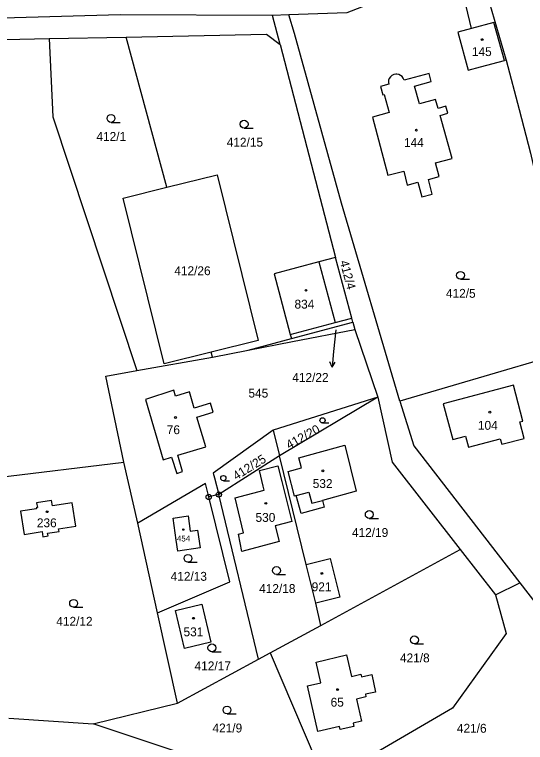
# Model space of a CAD drawing. Extents: x -725728 to -720881, y -1068679 to -1063504.
# Drawn here: x -724297.2 to -724199.5, y -1067188.2 to -1067048.9 of the extents above; entities that cross this region are included whole.
import ezdxf

# ---------------------------------------------------------------- set-up
doc = ezdxf.new("R2010")
doc.units = 0
for name, color, linetype in [('Hranice parcel', 7, 'Continuous'), ('Parcelní čísla', 7, 'Continuous'), ('Pop  PČ popisy', 7, 'Continuous'), ('Vnitřní kresba', 7, 'Continuous'), ('Značky bodu BP', 7, 'Continuous'), ('Značky budov', 7, 'Continuous'), ('Značky kultur', 7, 'Continuous')]:
    doc.layers.add(name, color=color, linetype=linetype)

# ---------------------------------------------------------------- blocks, each defined once
blk = doc.blocks.new('4.02_3')
at = {"layer": 'Značky budov'}
blk.add_circle((-0.001, 0), 0.0175, dxfattribs=at)
blk = doc.blocks.new('4.02_4')
at = {"layer": 'Značky budov'}
blk.add_circle((-0.001, 0), 0.0175, dxfattribs=at)
blk = doc.blocks.new('4.02_2')
at = {"layer": 'Značky budov'}
blk.add_circle((0, 0), 0.0117, dxfattribs=at)
blk = doc.blocks.new('1029_89')
at = {"layer": 'Pop  PČ popisy'}
for p, q in [((0, 0), (-0.031, -0.299)), ((-0.031, -0.299), (-0.071, -0.194)), ((-0.031, -0.299), (0.029, -0.204))]:
    blk.add_line(p, q, dxfattribs=at)
blk = doc.blocks.new('3.04_2')
at = {"layer": 'Značky kultur'}
blk.add_line((0.001, 0), (0.176, 0), dxfattribs=at)
blk.add_circle((0.001, 0.075), 0.075, dxfattribs=at)
blk = doc.blocks.new('3.04_4')
at = {"layer": 'Značky kultur'}
blk.add_line((0, 0), (0.118, 0), dxfattribs=at)
blk.add_circle((0, 0.05), 0.0502, dxfattribs=at)
blk = doc.blocks.new('3.04_5')
at = {"layer": 'Značky kultur'}
blk.add_line((0, 0), (0.118, 0), dxfattribs=at)
blk.add_circle((0, 0.05), 0.0502, dxfattribs=at)
blk = doc.blocks.new('1.05_1')
at = {"layer": 'Značky bodu BP'}
for radius in [0.05, 0.00303]:
    blk.add_circle((0, 0), radius, dxfattribs=at)

msp = doc.modelspace()

# ---------------------------------------------------------------- linework, layer by layer
at = {"layer": 'Hranice parcel'}
for p, q in [((-724244.76, -1067048.93), (-724247.87, -1067049.04)), ((-724246.42, -1067054.59), (-724247.87, -1067049.04)), ((-724209.79, -1067051.55), (-724212.38, -1067052.24)), ((-724290.63, -1067053.45), (-724275.88, -1067053.19)), ((-724268.12, -1067081.94), (-724275.88, -1067053.19)), ((-724212.38, -1067052.24), (-724210.45, -1067059.55)), ((-724246.42, -1067054.59), (-724235.83, -1067095.37)), ((-724203.19, -1067057.61), (-724203.49, -1067057.69)), ((-724235.83, -1067095.37), (-724239.02, -1067096.23)), ((-724244.26, -1067110.92), (-724232.5, -1067107.77)), ((-724232.5, -1067107.77), (-724232.13, -1067109.15)), ((-724232.13, -1067109.15), (-724227.7, -1067122.1)), ((-724244.47, -1067110.14), (-724244.26, -1067110.92)), ((-724252.55, -1067113.14), (-724244.26, -1067110.92)), ((-724259.34, -1067114.48), (-724252.55, -1067113.14)), ((-724190, -1067113), (-724223.48, -1067122.9)), ((-724273.83, -1067117.04), (-724259.34, -1067114.48)), ((-724259.34, -1067114.48), (-724259.6, -1067113.52)), ((-724272.19, -1067122.6), (-724268.81, -1067134.1)), ((-724227.7, -1067122.1), (-724247.76, -1067128.45)), ((-724227.7, -1067122.1), (-724246.55, -1067133.36)), ((-724247.76, -1067128.45), (-724246.55, -1067133.36)), ((-724242.83, -1067133.72), (-724234.05, -1067131.33)), ((-724246.55, -1067133.36), (-724258.14, -1067140.77)), ((-724241.43, -1067154.16), (-724246.55, -1067133.36)), ((-724328.2, -1067140.88), (-724276.31, -1067134.54)), ((-724273.68, -1067146.26), (-724276.31, -1067134.54)), ((-724258.14, -1067140.77), (-724260.09, -1067141.24)), ((-724250.56, -1067172.31), (-724258.14, -1067140.77)), ((-724296.14, -1067143.96), (-724295.41, -1067148.42)), ((-724269.88, -1067163.39), (-724273.68, -1067146.26)), ((-724238.63, -1067165.85), (-724211.97, -1067151.3)), ((-724211.97, -1067151.3), (-724205.22, -1067159.99)), ((-724239.57, -1067161.57), (-724241.43, -1067154.16)), ((-724205.22, -1067159.99), (-724200.52, -1067157.7)), ((-724200.52, -1067157.7), (-724197.03, -1067162.21)), ((-724238.63, -1067165.85), (-724239.57, -1067161.57)), ((-724266.04, -1067180.69), (-724269.88, -1067163.39)), ((-724248.33, -1067171.1), (-724238.63, -1067165.85)), ((-724250.56, -1067172.31), (-724248.33, -1067171.1)), ((-724248.33, -1067171.1), (-724238.81, -1067193.3)), ((-724266.04, -1067180.69), (-724250.56, -1067172.31)), ((-724282.2, -1067184.67), (-724266.04, -1067180.69)), ((-724298.36, -1067183.59), (-724282.2, -1067184.67))]:
    msp.add_line(p, q, dxfattribs=at)
for points in [[(-724207.25, -1067043.58), (-724203.24, -1067057.41), (-724203.19, -1067057.61)], [(-724223.6, -1067044.73), (-724230.84, -1067047.46), (-724233.67, -1067048.56), (-724244.76, -1067048.93)], [(-724209.79, -1067051.55), (-724211.49, -1067044.28), (-724211.58, -1067043.89)], [(-724247.87, -1067049.04), (-724277.04, -1067048.9), (-724322.02, -1067050.23), (-724344.89, -1067051.13)], [(-724223.48, -1067122.9), (-724234.66, -1067084.98), (-724243.69, -1067052.47), (-724244.76, -1067048.93)], [(-724203.49, -1067057.69), (-724205.5, -1067050.42), (-724209.79, -1067051.55)], [(-724336.65, -1067073.56), (-724333.05, -1067073.26), (-724323.49, -1067072.46), (-724323.36, -1067073.88), (-724319.81, -1067073.57), (-724320.87, -1067060.76), (-724321.59, -1067054.14), (-724290.63, -1067053.45)], [(-724290.63, -1067053.45), (-724289.95, -1067068.44), (-724273.83, -1067117.04)], [(-724275.88, -1067053.19), (-724249, -1067052.63), (-724246.42, -1067054.59)], [(-724210.45, -1067059.55), (-724208.08, -1067058.88), (-724203.49, -1067057.69)], [(-724203.19, -1067057.61), (-724200.67, -1067067.06), (-724198.5, -1067075.42), (-724192.22, -1067103.19)], [(-724225.64, -1067062.23), (-724227.2, -1067062.65), (-724226.77, -1067064.23), (-724226.53, -1067064.17), (-724225.57, -1067067.6), (-724228.75, -1067068.49), (-724225.83, -1067079.65), (-724222.77, -1067078.85), (-724222.08, -1067081.51), (-724220.04, -1067080.98), (-724219.3, -1067083.79), (-724217.31, -1067083.27), (-724218.05, -1067080.46), (-724215.96, -1067079.91), (-724216.66, -1067077.25), (-724213.51, -1067076.42), (-724215.82, -1067068.19), (-724214.35, -1067067.78), (-724214.73, -1067066.43), (-724216.2, -1067066.84), (-724216.69, -1067065.11), (-724219.77, -1067065.97), (-724220.72, -1067062.6), (-724217.54, -1067061.68), (-724217.92, -1067060.14), (-724222.71, -1067061.44)], [(-724222.71, -1067061.44), (-724222.85, -1067061.07), (-724223.07, -1067060.76), (-724223.37, -1067060.51), (-724223.72, -1067060.34), (-724224.11, -1067060.27), (-724224.29, -1067060.27), (-724224.67, -1067060.35), (-724225.02, -1067060.52), (-724225.32, -1067060.77), (-724225.54, -1067061.09), (-724225.67, -1067061.46), (-724225.71, -1067061.85), (-724225.64, -1067062.23)], [(-724268.12, -1067081.94), (-724258.45, -1067079.55), (-724250.61, -1067111.3), (-724259.6, -1067113.52)], [(-724259.6, -1067113.52), (-724268.6, -1067115.74), (-724276.45, -1067084), (-724268.12, -1067081.94)], [(-724239.02, -1067096.23), (-724247.56, -1067098.51), (-724244.47, -1067110.14)], [(-724232.5, -1067107.77), (-724232.71, -1067106.99), (-724235.83, -1067095.37)], [(-724252.55, -1067113.14), (-724244.04, -1067111.48), (-724232.13, -1067109.15)], [(-724276.31, -1067134.54), (-724279.78, -1067118.09), (-724273.83, -1067117.04)], [(-724210.38, -1067131.69), (-724204.28, -1067130.09), (-724204.01, -1067131.15), (-724199.7, -1067130.02), (-724200.52, -1067126.88), (-724199.94, -1067126.73), (-724201.74, -1067119.86), (-724215.19, -1067123.38), (-724213.39, -1067130.25), (-724210.92, -1067129.61), (-724210.38, -1067131.69)], [(-724268.81, -1067134.1), (-724267.23, -1067133.59), (-724266.16, -1067136.72), (-724265.11, -1067136.35), (-724265.97, -1067133.23), (-724260.67, -1067131.62), (-724262.35, -1067125.94), (-724259.26, -1067124.99), (-724259.77, -1067123.29), (-724262.86, -1067124.22), (-724263.78, -1067121.12), (-724266.43, -1067121.93), (-724266.79, -1067120.81), (-724272.19, -1067122.6)], [(-724227.7, -1067122.1), (-724224.97, -1067134.56), (-724211.97, -1067151.3)], [(-724223.48, -1067122.9), (-724220.85, -1067131.46), (-724200.52, -1067157.7)], [(-724247.76, -1067128.45), (-724259.24, -1067136.68), (-724259, -1067137.58), (-724258.14, -1067140.77)], [(-724234.05, -1067131.33), (-724231.85, -1067140.12), (-724238.33, -1067141.88), (-724237.97, -1067143.19), (-724242.41, -1067144.4), (-724243.35, -1067140.97), (-724243.64, -1067141.05), (-724244.91, -1067136.36), (-724242.3, -1067135.65), (-724242.83, -1067133.72)], [(-724253.41, -1067148.11), (-724255.03, -1067141.38), (-724249.48, -1067139.94), (-724249.65, -1067139.16), (-724250.37, -1067136.15), (-724246.84, -1067135.28), (-724246.1, -1067138.29), (-724244.21, -1067145.94), (-724247.35, -1067146.79), (-724246.59, -1067149.75), (-724253.75, -1067151.66), (-724254.41, -1067148.37), (-724253.41, -1067148.11)], [(-724260.09, -1067141.24), (-724260.73, -1067138.68), (-724273.68, -1067146.26)], [(-724269.88, -1067163.39), (-724256.05, -1067157.5), (-724260.09, -1067141.24)], [(-724295.41, -1067148.42), (-724291.99, -1067147.86), (-724291.83, -1067148.85), (-724290.84, -1067148.69), (-724290.92, -1067148.19), (-724288.74, -1067147.84), (-724288.82, -1067147.34), (-724285.5, -1067146.8), (-724286.23, -1067142.34), (-724290, -1067142.95), (-724290.17, -1067141.91), (-724293.04, -1067142.38), (-724292.89, -1067143.28), (-724293.09, -1067143.31), (-724293.06, -1067143.51), (-724296.14, -1067143.96)], [(-724264.04, -1067144.86), (-724263.62, -1067147.79), (-724262.25, -1067147.61), (-724261.7, -1067150.96), (-724266.02, -1067151.58), (-724266.32, -1067149.49), (-724266.92, -1067145.27), (-724264.04, -1067144.86)], [(-724241.43, -1067154.16), (-724236.82, -1067153.01), (-724234.98, -1067160.43), (-724239.57, -1067161.57)], [(-724205.22, -1067159.99), (-724203.14, -1067167.35), (-724213.41, -1067181.65), (-724227.23, -1067189.7), (-724238.81, -1067193.3)], [(-724264.7, -1067170.27), (-724266.43, -1067162.97), (-724261.43, -1067161.76), (-724259.68, -1067169.02), (-724264.7, -1067170.27)], [(-724230.95, -1067175.17), (-724230.84, -1067175.65), (-724228.89, -1067175.22), (-724228.15, -1067178.59), (-724230.11, -1067179.02), (-724230, -1067179.51), (-724231.8, -1067179.96), (-724230.87, -1067184.17), (-724232.45, -1067184.56), (-724232.32, -1067185.18), (-724234.9, -1067185.78), (-724235.05, -1067185.15), (-724239.18, -1067186.11), (-724241.21, -1067177.4), (-724238.65, -1067176.84), (-724239.52, -1067172.84), (-724233.71, -1067171.48), (-724232.75, -1067175.6), (-724230.95, -1067175.17)], [(-724238.81, -1067193.3), (-724248.42, -1067195.98), (-724282.2, -1067184.67)]]:
    msp.add_lwpolyline(points, dxfattribs=at)
at = {"layer": 'Pop  PČ popisy'}
msp.add_line((-724235.75, -1067109.21), (-724236.18, -1067113.39), dxfattribs=at)
at = {"layer": 'Vnitřní kresba'}
for p, q in [((-724239.02, -1067096.23), (-724235.9, -1067107.84)), ((-724244.47, -1067110.14), (-724235.9, -1067107.84)), ((-724235.9, -1067107.84), (-724232.71, -1067106.99)), ((-724243.35, -1067140.97), (-724240.93, -1067140.32)), ((-724240.93, -1067140.32), (-724240.35, -1067142.44)), ((-724240.35, -1067142.44), (-724238.33, -1067141.88))]:
    msp.add_line(p, q, dxfattribs=at)

# ---------------------------------------------------------------- block references
at = {"layer": 'Pop  PČ popisy', "xscale": 10, "yscale": 10}
msp.add_blockref('1029_89', (-724236.18, -1067113.39), dxfattribs=at)
at = {"layer": 'Značky bodu BP', "xscale": 10, "yscale": 10}
for p in [(-724260.09, -1067141.24), (-724258.14, -1067140.77)]:
    msp.add_blockref('1.05_1', p, dxfattribs=at)
at = {"layer": 'Značky budov', "xscale": 10, "yscale": 10}
for name, p in [('4.02_4', (-724207.75, -1067053.67)), ('4.02_3', (-724220.34, -1067071.02)), ('4.02_4', (-724241.46, -1067101.67)), ('4.02_3', (-724266.45, -1067126.01)), ('4.02_3', (-724206.28, -1067125)), ('4.02_3', (-724238.21, -1067136.23)), ('4.02_3', (-724249.16, -1067142.45)), ('4.02_3', (-724291.01, -1067144.06)), ('4.02_2', (-724264.95, -1067147.48)), ('4.02_3', (-724238.41, -1067155.87)), ('4.02_3', (-724263, -1067164.46)), ('4.02_3', (-724235.41, -1067178.12))]:
    msp.add_blockref(name, p, dxfattribs=at)
at = {"layer": 'Značky kultur', "xscale": 10, "yscale": 10}
for name, p in [('3.04_2', (-724278.8, -1067069.51)), ('3.04_2', (-724253.33, -1067070.61)), ('3.04_2', (-724211.92, -1067099.55)), ('3.04_4', (-724238.3, -1067127.07)), ('3.04_5', (-724257.29, -1067138.13)), ('3.04_2', (-724229.37, -1067145.34)), ('3.04_2', (-724264.07, -1067153.73)), ('3.04_2', (-724247.13, -1067156.07)), ('3.04_2', (-724285.96, -1067162.34)), ('3.04_2', (-724220.72, -1067169.35)), ('3.04_2', (-724259.49, -1067170.87)), ('3.04_2', (-724256.6, -1067182.77))]:
    msp.add_blockref(name, p, dxfattribs=at)

# ---------------------------------------------------------------- texts
at = {"layer": 'Parcelní čísla'}
for s, height, p in [('145', 1.7, (-724209.72, -1067056.82)), ('412/1', 1.7, (-724281.58, -1067073.06)), ('412/15', 1.7, (-724256.64, -1067074.16)), ('144', 1.7, (-724222.72, -1067074.23)), ('412/26', 1.7, (-724266.68, -1067098.77)), ('412/5', 1.7, (-724214.69, -1067103.1)), ('834', 1.7, (-724243.67, -1067105.17)), ('412/22', 1.7, (-724244.1, -1067119.2)), ('545', 1.7, (-724252.49, -1067122.2)), ('104', 1.7, (-724208.57, -1067128.37)), ('76', 1.7, (-724268.12, -1067129.21)), ('532', 1.7, (-724240.18, -1067139.52)), ('236', 1.7, (-724292.98, -1067147.03)), ('530', 1.7, (-724251.13, -1067146)), ('412/19', 1.7, (-724232.68, -1067148.89)), ('454', 1.14, (-724266.18, -1067149.76)), ('412/13', 1.7, (-724267.38, -1067157.28)), ('412/18', 1.7, (-724250.44, -1067159.62)), ('921', 1.7, (-724240.38, -1067159.28)), ('412/12', 1.7, (-724289.27, -1067165.89)), ('531', 1.7, (-724264.91, -1067167.91)), ('421/8', 1.7, (-724223.49, -1067172.9)), ('412/17', 1.7, (-724262.8, -1067174.42)), ('65', 1.7, (-724236.76, -1067181.38)), ('421/9', 1.7, (-724259.37, -1067186.32)), ('421/6', 1.7, (-724212.59, -1067186.37))]:
    msp.add_text(s, height=height, dxfattribs=at).set_placement(p)
for s, rotation, p in [('412/4', 285, (-724235.03, -1067096.17)), ('412/20', 29, (-724244.7, -1067132.15)), ('412/25', 32, (-724254.83, -1067138.1))]:
    msp.add_text(s, height=1.7, rotation=rotation, dxfattribs=at).set_placement(p)

doc.saveas('drawing.dxf')
